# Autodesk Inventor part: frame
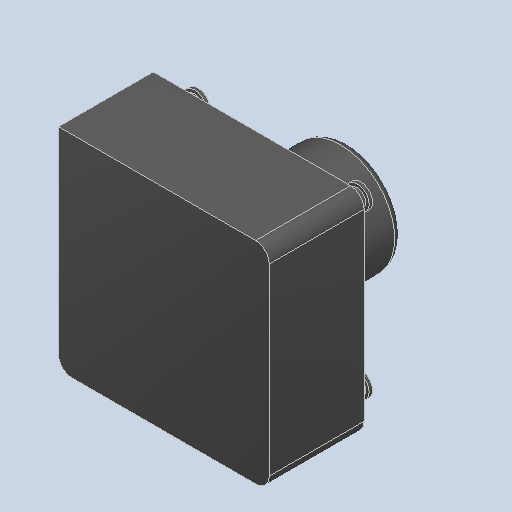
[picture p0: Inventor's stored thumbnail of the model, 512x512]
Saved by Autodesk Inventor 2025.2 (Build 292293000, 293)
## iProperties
Created: 2025-04
Part Number: frame
Material: Generic
Description: PART-frame-DESC
Document SubType Name: Modeling
Designer: BennF
Density: 1 g/cm^3
Appearance: Default
Author: BennF
Revision Number: NONE
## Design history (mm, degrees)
feature "Solid"
body "Solid1"
